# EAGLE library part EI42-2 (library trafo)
TRANSFORMER 1 primary winding, 2 secondary windings ERA
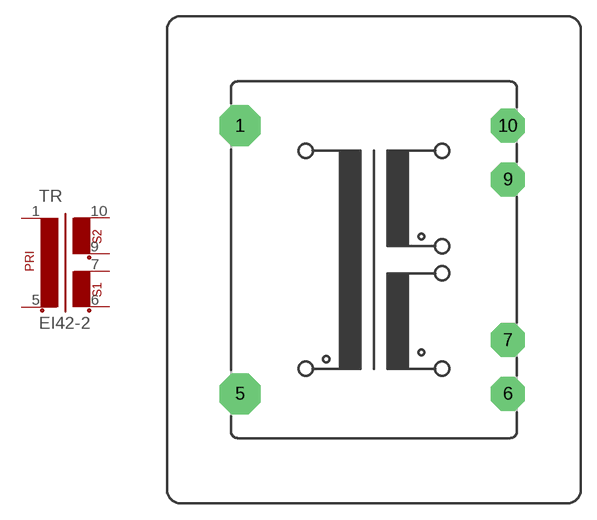
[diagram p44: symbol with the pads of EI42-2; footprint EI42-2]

Designator prefix TR

## EI42-2  [EI42-2]
1  1  pas
5  2  pas
6  3  pas
7  4  pas
9  5  pas
10  6  pas

## Footprint EI42-2 (pad centres in mm)
TRANSFORMER 1 primary winding, 2 secondary windings
drill 1.118 pad 3.81 octagon: 1 -12.497,12.497; 5 -12.497,-12.497
drill 1.118 pad 3.175 octagon: 6 12.497,-12.497; 7 12.497,-7.493; 9 12.497,7.493; 10 12.497,12.497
